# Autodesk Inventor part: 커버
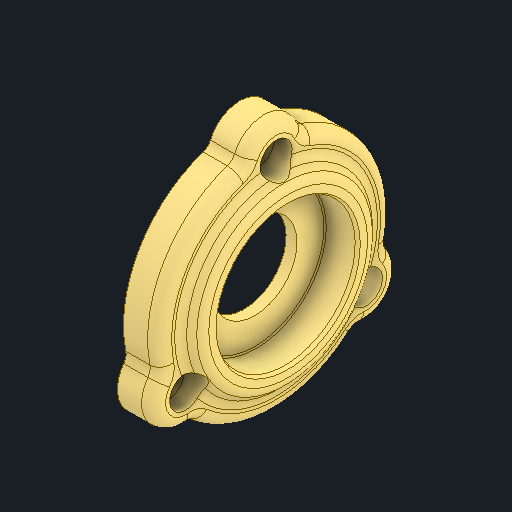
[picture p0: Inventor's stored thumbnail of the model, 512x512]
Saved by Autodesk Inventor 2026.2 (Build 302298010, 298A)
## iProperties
Created: 2026-03
Part Number: 커버
Material: 알루미늄 6061
Document SubType Name: Modeling
Designer: PC2-02
Density: 2.7 g/cm^3
Appearance: 기본값
Author: jhkim
Sending System: Autodesk Inventor 2026
Preprocessor: ST-DEVELOPER v20.1
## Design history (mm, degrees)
feature "솔리드1"
node "솔리드2"
